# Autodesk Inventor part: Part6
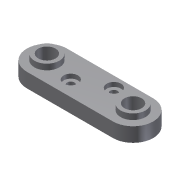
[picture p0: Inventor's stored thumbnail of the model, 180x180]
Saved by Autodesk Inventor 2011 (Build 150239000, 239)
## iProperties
Shininess: 77.0
Length Units: 11269
Angle Units: 11279
Time Units: 11290
Mass Units: 11283
Length Display Precision: 3
Angle Display Precision: 2
Created: 2002-01
Part Number: Part6
Document SubType Name: Modeling
Designer: ***
Density: 1 g/cm^3
Mass: 21.6911 g
Surface Area: 77.1136 cm^2
Volume: 21.6911 cm^3
Density: 0.0
Volumn: 0.0
Area: 0.0
PropertySet Name: Model Information
Control State: 0
Master: False
Checked Out: False
Author: ***
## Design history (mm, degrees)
sketch "Sketch1"
  geometry: L1 (-33.118, 12.346)-(26.882, 12.361); L2 (-33.111, -15.654)-(26.889, -15.639); C1 r 6 at (-33.114, -1.654); C2 r 6 at (26.886, -1.639); A1 r 14 centre (-33.114, -1.654) between (-33.118, 12.346) and (-33.111, -15.654); A2 r 14 centre (26.886, -1.639) between (26.889, -15.639) and (26.882, 12.361)
  constraints: 4 centre point, 4 end point, 4 point on circle, 4 tangent, 2 coincident, 2 equal radius
  dimensions: "d0" = 60 distance of L1.start L1.end; "d1" = 14 radius of A1; "d2" = 12 diameter of C1
extrude "Extrusion1" new body sketch "Sketch1" distance "d3" = 10; taper "d4" = 0 deg
sketch "Sketch2"
  geometry: C1 r 6 at (26.886, -1.639) reference; C2 r 6 at (-33.114, -1.654) reference; C3 r 8.694 at (-33.114, -1.654); C4 r 8.694 at (26.886, -1.639)
  constraints: 2 centre point, 2 coincident, 1 equal radius
extrude "Extrusion2" join sketch "Sketch2" distance "d5" = 4; taper "d6" = 0 deg
sketch "Sketch3"
  geometry: C1 r 8.694 at (-33.114, -1.654) reference; C2 r 8.694 at (26.886, -1.639) reference; 3 further points
  dimensions: "d7" = 20 horizontal distance of C1.centre point (-13.114, -5); "d8" = 20 horizontal distance of C2.centre point (6.886, 5); "d9" = 5 vertical distance of point (0, 0) point (6.886, 5); "d10" = 5 vertical distance of point (-13.114, -5) point (0, 0)
hole "Hole1" sketch "Sketch3" at (-13.114, -5), (6.886, 5) diameter "d11" = 5; stored, may be unused: countersink angle "d15" = 90 deg, drill point angle "d17" = 0 deg; dims "d12" = 6, "d13" = 10, "d14" = 3, "d16" = 8
body "Solid1"
